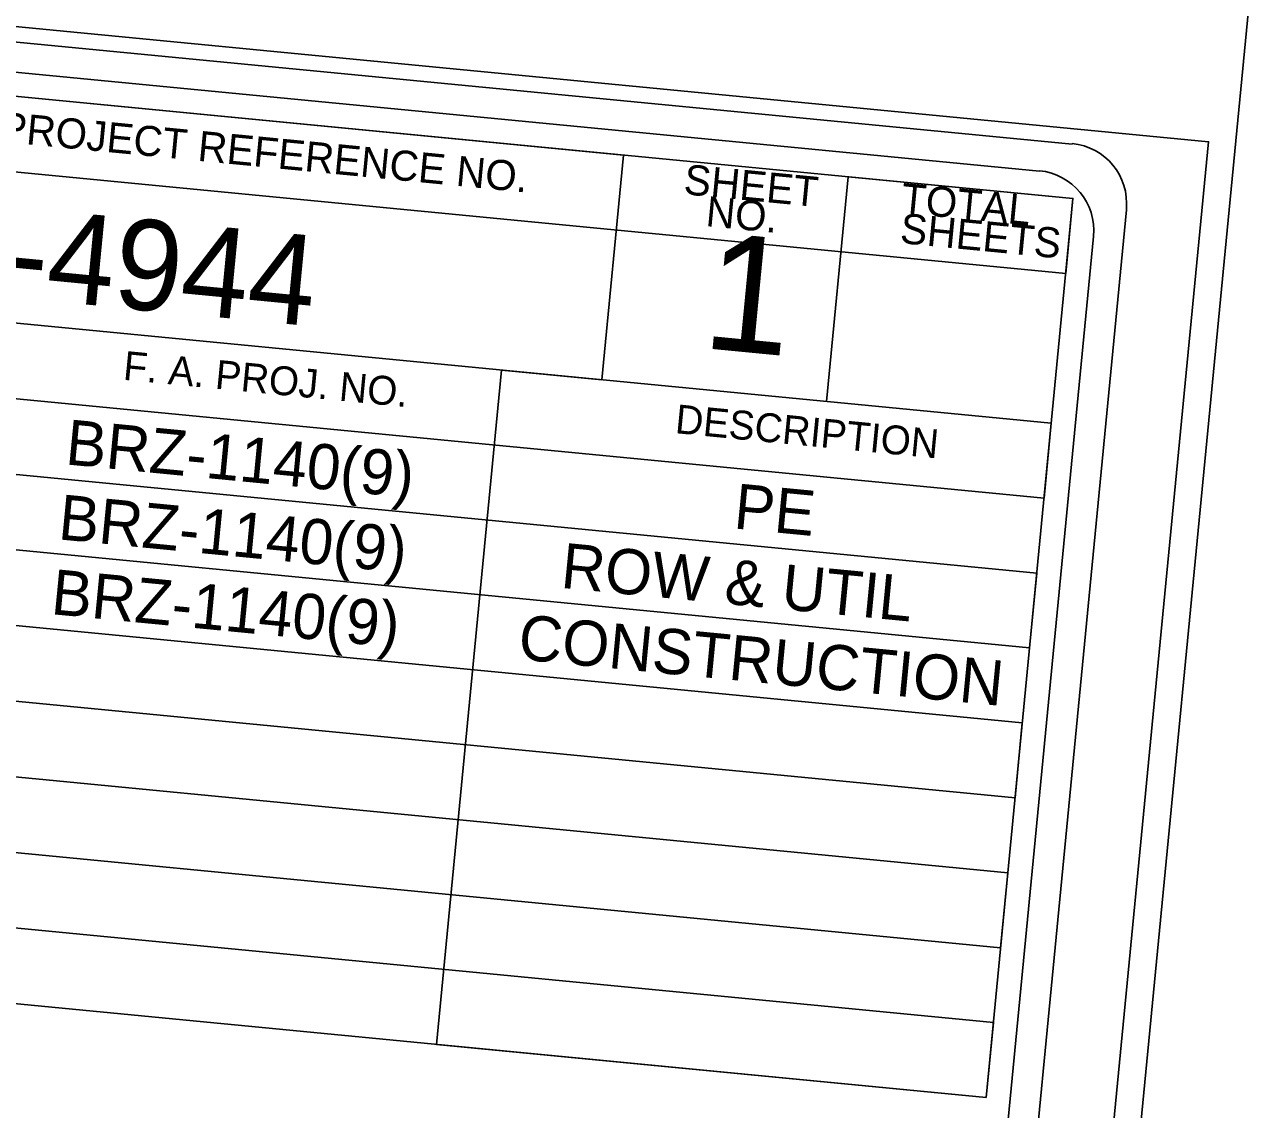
# Model space of a CAD drawing. Extents: x 2060574 to 2063008, y 912203 to 913082.
# Drawn here: x 2061521.3 to 2061643.3, y 912875.4 to 912983.6 of the extents above; entities that cross this region are included whole.
import ezdxf

# ---------------------------------------------------------------- set-up
doc = ezdxf.new("R2010")
doc.units = 0
for name, color, linetype in [('Sheet Data Field CELL', 7, 'Continuous'), ('Sheet Plot Border Inside CELL', 7, 'Continuous'), ('Sheet Plot Border Outside CELL', 7, 'Continuous'), ('Sheet Title CELL', 7, 'Continuous')]:
    doc.layers.add(name, color=color, linetype=linetype)

msp = doc.modelspace()

# ---------------------------------------------------------------- linework, layer by layer
at = {"layer": 'Sheet Plot Border Inside CELL'}
msp.add_lwpolyline([(2060583.16, 912437.96), (2061578.42, 912341.76), (2061639.33, 912971.88), (2060644.07, 913068.09)], close=True, dxfattribs=at)
at = {"layer": 'Sheet Plot Border Outside CELL'}
msp.add_lwpolyline([(2061643.31, 912985.03), (2060637.6, 913082.24), (2060574.1, 912425.31), (2061579.81, 912328.1)], close=True, dxfattribs=at)
at = {"layer": 'Sheet Title CELL'}
for points in [[(2061625.75, 912971.65), (2060741.86, 913057.1)], [(2061622.47, 912968.96), (2060774.43, 913050.93)], [(2061460.87, 912974.64), (2061625.1, 912958.76), (2061625.82, 912966.23), (2061461.59, 912982.1)], [(2061483.99, 912979.94), (2061581.04, 912970.55), (2061578.87, 912948.16), (2061568.89, 912949.13), (2061562.4, 912881.94), (2061617.16, 912876.65), (2061625.82, 912966.23), (2061603.43, 912968.39), (2061601.27, 912946)], [(2061571.68, 912349.98), (2061631.14, 912965.11)], [(2061579.66, 912463.73), (2061627.87, 912962.42)], [(2061458.7, 912952.24), (2061622.94, 912936.36), (2061623.66, 912943.83), (2061459.42, 912959.71)], [(2061457.26, 912937.31), (2061621.49, 912921.44), (2061622.22, 912928.9), (2061457.98, 912944.77)], [(2061455.82, 912922.38), (2061620.05, 912906.51), (2061620.77, 912913.97), (2061456.54, 912929.85)], [(2061454.37, 912907.45), (2061618.61, 912891.57), (2061619.33, 912899.04), (2061455.1, 912914.91)], [(2061452.93, 912892.52), (2061617.16, 912876.65), (2061617.89, 912884.11), (2061453.65, 912899.99)]]:
    msp.add_lwpolyline(points, dxfattribs=at)
for centre in [(2061625.17, 912965.72), (2061621.9, 912963.02)]:
    msp.add_arc(centre, 6, 354.4787, 84.4787, dxfattribs=at)

# ---------------------------------------------------------------- texts
at = {"layer": 'Sheet Data Field CELL'}
for s, height, p in [('B-4944', 9, (2061511.34, 912957.22)), ('BRZ-1140(9)', 4.5, (2061525.33, 912939.74)), ('PE', 4.5, (2061591.92, 912933.36)), ('BRZ-1140(9)', 4.5, (2061524.61, 912932.27)), ('ROW & UTIL', 4.5, (2061574.69, 912927.44)), ('BRZ-1140(9)', 4.5, (2061523.89, 912924.82)), ('CONSTRUCTION', 4.5, (2061570.43, 912920.32))]:
    msp.add_text(s, height=height, rotation=354.4787, dxfattribs=at).set_placement(p)
at = {"layer": 'Sheet Title CELL'}
for s, height, p in [('STATE PROJECT REFERENCE NO.', 2.9999, (2061504.8, 912973.25)), ('SHEET', 3, (2061586.96, 912966.66)), ('TOTAL', 3, (2061608.6, 912964.79)), ('NO.', 3, (2061589.15, 912963.48)), ('SHEETS', 3, (2061608.51, 912961.79)), ('1', 11.61, (2061588.73, 912951.34)), ('F. A. PROJ. NO.', 2.88, (2061531.1, 912948.17)), ('DESCRIPTION', 2.88, (2061586.1, 912942.85))]:
    msp.add_text(s, height=height, rotation=354.4787, dxfattribs=at).set_placement(p)

doc.saveas('drawing.dxf')
